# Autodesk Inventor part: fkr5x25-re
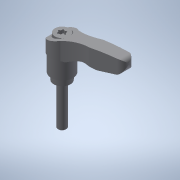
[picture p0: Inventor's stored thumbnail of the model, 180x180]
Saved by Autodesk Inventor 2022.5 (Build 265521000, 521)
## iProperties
Created: 2017-09
Part Number: fkr5x25-re
Material: 一般
Document SubType Name: Modeling
Designer: imaocorp
Density: 1 g/cm^3
Appearance: 既定
Author: imaocorp
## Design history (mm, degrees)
node "fkr5x25-re.x_t1"
node "fkr5x25-re"
node "Base1"
